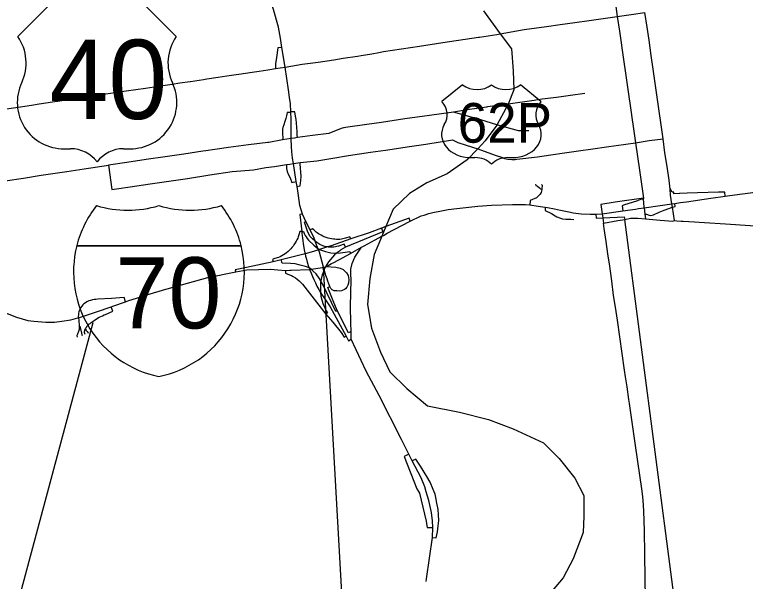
# Model space of a CAD drawing. Extents: x -1146 to -445, y -1283 to -822.
# Drawn here: x -909.25 to -877.16, y -1082.3 to -1057.42 of the extents above; entities that cross this region are included whole.
import ezdxf

# ---------------------------------------------------------------- set-up
doc = ezdxf.new("R2010")
doc.units = 0
for name, color, linetype in [('Default', 7, 'Continuous'), ('GM_P_US_Alignment', 7, 'Continuous'), ('GM_P_US_Shield', 7, 'Continuous'), ('GM_X_Interchange_Ramps', 7, 'Continuous'), ('GM_X_Interstate_Route', 7, 'Continuous'), ('GM_X_Interstate_Shield', 7, 'Continuous'), ('GM_X_State_Route', 7, 'Continuous'), ('GM_X_Township', 7, 'Continuous'), ('GM_X_US_Route', 7, 'Continuous'), ('GM_X_US_Shield', 7, 'Continuous')]:
    doc.layers.add(name, color=color, linetype=linetype)

msp = doc.modelspace()

# ---------------------------------------------------------------- linework, layer by layer
at = {"layer": 'Default'}
for points in [[(-877.164, -1087.481), (-879.711, -1087.481), (-882.459, -1066.411)], [(-897.172, -1087.481), (-894.625, -1087.481), (-895.684, -1068.512)], [(-914.692, -1094.509), (-912.144, -1094.509), (-905.796, -1070.942)]]:
    msp.add_lwpolyline(points, dxfattribs=at)
at = {"layer": 'GM_P_US_Alignment'}
msp.add_lwpolyline([(-886.673, -1062.523), (-887.13, -1062.531), (-888.071, -1062.256), (-888.783, -1062.047), (-889.976, -1061.698)], dxfattribs=at)
at = {"layer": 'GM_P_US_Shield'}
for p, q in [((-889.583, -1060.507), (-890.489, -1061.232)), ((-886.139, -1061.232), (-887.045, -1060.507)), ((-889.22, -1063.698), (-889.039, -1063.698)), ((-887.589, -1063.698), (-887.408, -1063.698))]:
    msp.add_line(p, q, dxfattribs=at)
for centre, major_axis, start_param, end_param in [((-888.948, -1059.989), (-0.906, 0), 0.795399, 2.346194), ((-887.68, -1059.989), (-0.906, 0), 0.795399, 2.346194), ((-891.529, -1061.815), (1.269, 0), 5.838949, 6.894067), ((-885.099, -1061.815), (-1.269, 0), 5.672304, 6.727422), ((-889.235, -1062.683), (1.269, 0), 2.702327, 4.723529), ((-887.393, -1062.683), (-1.269, 0), 1.559657, 3.580859), ((-889.039, -1064.423), (-0.906, 0), 3.785094, 4.712389), ((-887.589, -1064.423), (-0.906, 0), 4.712389, 5.639684)]:
    msp.add_ellipse(centre, major_axis=major_axis, ratio=0.8, start_param=start_param, end_param=end_param, dxfattribs=at)
at = {"layer": 'GM_X_Interchange_Ramps'}
for points in [[(-897.519, -1058.866), (-897.688, -1058.887), (-897.748, -1059.306), (-897.793, -1059.586), (-897.799, -1059.663), (-897.793, -1059.788)], [(-897.117, -1061.72), (-897.29, -1061.721), (-897.318, -1061.861), (-897.345, -1061.984), (-897.382, -1062.115), (-897.432, -1062.257), (-897.474, -1062.374), (-897.488, -1062.458), (-897.494, -1062.646), (-897.471, -1062.852), (-897.488, -1062.92)], [(-896.826, -1062.823), (-896.843, -1062.711), (-896.848, -1062.547), (-896.856, -1062.374), (-896.873, -1062.174), (-896.893, -1062.025), (-896.915, -1061.882), (-896.944, -1061.689), (-897.117, -1061.691)], [(-897.314, -1064.007), (-897.316, -1064.056), (-897.316, -1064.177), (-897.278, -1064.307), (-897.238, -1064.425), (-897.156, -1064.594), (-897.079, -1064.793), (-896.89, -1064.748)], [(-896.85, -1064.967), (-896.715, -1064.945), (-896.681, -1064.7), (-896.665, -1064.529), (-896.716, -1063.978), (-896.719, -1063.918)], [(-886.123, -1064.876), (-886.091, -1064.913), (-886.101, -1065.081), (-886.122, -1065.179), (-886.137, -1065.227), (-886.182, -1065.301), (-886.236, -1065.363), (-886.343, -1065.459), (-886.613, -1065.582), (-886.633, -1065.779)], [(-886.381, -1064.869), (-886.372, -1064.925), (-886.322, -1064.938), (-886.291, -1064.951), (-886.2, -1065.029), (-886.164, -1065.075), (-886.101, -1065.081)], [(-880.308, -1065.256), (-880.313, -1065.219), (-880.363, -1065.21), (-880.399, -1065.181), (-880.419, -1065.141), (-880.433, -1065.088), (-880.464, -1065.091)], [(-878.045, -1065.391), (-878.071, -1065.209), (-878.349, -1065.217), (-879.718, -1065.258), (-880.043, -1065.272), (-880.06, -1065.274), (-880.304, -1065.293), (-880.308, -1065.256)], [(-881.659, -1065.527), (-881.767, -1065.541), (-881.901, -1065.598), (-882.518, -1065.793), (-882.579, -1065.814), (-882.544, -1066.035)], [(-885.958, -1065.871), (-885.962, -1066.024), (-885.673, -1066.158), (-885.518, -1066.25), (-885.437, -1066.303), (-885.284, -1066.353), (-885.191, -1066.379), (-885.051, -1066.402), (-884.827, -1066.405), (-884.698, -1066.409)], [(-881.576, -1066.187), (-881.505, -1066.186), (-881.385, -1066.23), (-881.318, -1066.238), (-881.264, -1066.23), (-881.197, -1066.21), (-880.954, -1066.094), (-880.727, -1066.004), (-880.371, -1065.877), (-880.252, -1065.839), (-880.265, -1065.708)], [(-896.616, -1066.176), (-896.721, -1066.197), (-896.638, -1066.943), (-896.634, -1067.027), (-896.626, -1067.124), (-896.614, -1067.237), (-896.602, -1067.343), (-896.581, -1067.488), (-896.556, -1067.639), (-896.534, -1067.753), (-896.508, -1067.878), (-896.499, -1067.917), (-896.475, -1068.018), (-896.439, -1068.156), (-896.4, -1068.293), (-896.341, -1068.479), (-896.319, -1068.542), (-896.297, -1068.605), (-896.232, -1068.777), (-896.177, -1068.91), (-896.118, -1069.045), (-896.047, -1069.197), (-895.975, -1069.34), (-895.895, -1069.488), (-895.815, -1069.626), (-895.774, -1069.696), (-895.577, -1069.984), (-895.394, -1070.253), (-894.695, -1071.535), (-894.585, -1071.737), (-894.476, -1071.673)], [(-883.724, -1066.179), (-883.723, -1066.364), (-883.427, -1066.348), (-882.481, -1066.293), (-882.459, -1066.411)], [(-891.879, -1066.487), (-891.931, -1066.353), (-892.948, -1066.726), (-893.139, -1066.803), (-893.677, -1067.001), (-894.495, -1067.268), (-895.358, -1067.57), (-895.511, -1067.619), (-895.869, -1067.733), (-895.908, -1067.746), (-896.135, -1067.818), (-896.499, -1067.917), (-897.024, -1068.058), (-897.551, -1068.186), (-897.896, -1068.269), (-899.069, -1068.518), (-899.566, -1068.623), (-899.542, -1068.711)], [(-894.73, -1067.63), (-894.786, -1067.5), (-895.032, -1067.593), (-895.23, -1067.623), (-895.463, -1067.625), (-895.511, -1067.619), (-895.585, -1067.609), (-895.713, -1067.577), (-895.846, -1067.513), (-895.985, -1067.422), (-896.053, -1067.363), (-896.166, -1067.263), (-896.288, -1067.14), (-896.395, -1066.922), (-896.517, -1066.533), (-896.463, -1066.508)], [(-894.495, -1067.268), (-894.534, -1067.178), (-894.728, -1067.24), (-894.835, -1067.265), (-894.896, -1067.28), (-894.977, -1067.287), (-895.052, -1067.29), (-895.122, -1067.289), (-895.193, -1067.285), (-895.25, -1067.279), (-895.331, -1067.267), (-895.413, -1067.251), (-895.482, -1067.233), (-895.568, -1067.206), (-895.657, -1067.172), (-895.721, -1067.143), (-895.792, -1067.107), (-895.851, -1067.074), (-895.908, -1067.038), (-895.966, -1066.998), (-896.007, -1066.967), (-896.069, -1066.916), (-896.118, -1066.871), (-896.17, -1066.82), (-896.28, -1066.87)], [(-893.139, -1066.803), (-893.079, -1066.957), (-894.73, -1067.63), (-894.921, -1067.748), (-894.993, -1067.798), (-895.079, -1067.863), (-895.111, -1067.892), (-895.199, -1067.968), (-895.294, -1068.064), (-895.381, -1068.165), (-895.462, -1068.271), (-895.541, -1068.393), (-895.597, -1068.493), (-895.655, -1068.616), (-895.677, -1068.664), (-895.74, -1068.839), (-895.789, -1069.032), (-895.803, -1069.121), (-895.814, -1069.188), (-895.827, -1069.342), (-895.826, -1069.519), (-895.815, -1069.626), (-895.799, -1069.773), (-895.762, -1069.942), (-895.714, -1070.095), (-895.633, -1070.293), (-895.568, -1070.417), (-895.512, -1070.51), (-895.579, -1070.564)], [(-896.638, -1066.943), (-896.724, -1066.945), (-896.771, -1067.085), (-896.801, -1067.18), (-896.822, -1067.234), (-896.862, -1067.302), (-896.893, -1067.368), (-896.932, -1067.441), (-896.985, -1067.526), (-897.023, -1067.58), (-897.073, -1067.644), (-897.127, -1067.707), (-897.179, -1067.76), (-897.244, -1067.82), (-897.313, -1067.877), (-897.378, -1067.924), (-897.446, -1067.968), (-897.513, -1068.006), (-897.595, -1068.047), (-897.665, -1068.078), (-897.726, -1068.1), (-897.863, -1068.146), (-897.928, -1068.165), (-897.896, -1068.269)], [(-896.638, -1066.943), (-896.569, -1066.941), (-896.535, -1067.029), (-896.49, -1067.112), (-896.45, -1067.179), (-896.399, -1067.254), (-896.343, -1067.327), (-896.113, -1067.541), (-895.931, -1067.684), (-895.869, -1067.733), (-895.597, -1067.823), (-895.369, -1067.877), (-895.183, -1067.895), (-895.111, -1067.892), (-894.938, -1067.883), (-894.53, -1067.823), (-894.503, -1067.901)], [(-895.084, -1070.414), (-895.152, -1070.448), (-895.735, -1069.237), (-895.803, -1069.121), (-895.878, -1068.993), (-896.017, -1068.802), (-896.143, -1068.679), (-896.237, -1068.602), (-896.319, -1068.542), (-896.484, -1068.475), (-896.708, -1068.413), (-896.927, -1068.356), (-897.142, -1068.346), (-897.51, -1068.336), (-897.551, -1068.186)], [(-897.355, -1068.649), (-897.351, -1068.778), (-897.188, -1068.837), (-897.093, -1068.879), (-897.015, -1068.92), (-896.925, -1068.975), (-896.843, -1069.034), (-896.758, -1069.105), (-896.692, -1069.168), (-896.609, -1069.26), (-895.579, -1070.564), (-895.273, -1070.914), (-894.914, -1071.37), (-894.776, -1071.58), (-894.695, -1071.535)], [(-894.476, -1071.33), (-894.585, -1071.389), (-895.084, -1070.414), (-895.265, -1069.981), (-895.492, -1069.398), (-895.415, -1069.352)], [(-904.386, -1070.031), (-904.447, -1069.842), (-904.998, -1069.878), (-905.595, -1069.916), (-905.683, -1069.922), (-905.753, -1069.931), (-905.837, -1069.946), (-905.916, -1069.966), (-905.997, -1069.992), (-906.081, -1070.031), (-906.144, -1070.07), (-906.206, -1070.118), (-906.255, -1070.164), (-906.303, -1070.221), (-906.339, -1070.271), (-906.373, -1070.329), (-906.403, -1070.395), (-906.426, -1070.462), (-906.441, -1070.522), (-906.453, -1070.604), (-906.456, -1070.676), (-906.453, -1070.73), (-906.452, -1070.748), (-906.439, -1070.827), (-906.417, -1071.096), (-906.415, -1071.141), (-906.417, -1071.193), (-906.422, -1071.241), (-906.431, -1071.286), (-906.444, -1071.333), (-906.456, -1071.37), (-906.473, -1071.41), (-906.491, -1071.448), (-906.526, -1071.509), (-906.5, -1071.586)], [(-906.007, -1071.415), (-906.033, -1071.341), (-906.068, -1071.328), (-906.092, -1071.305), (-906.113, -1071.263), (-906.128, -1071.208), (-906.105, -1071.151), (-906.085, -1071.121), (-906.062, -1071.087), (-906.028, -1071.048), (-905.989, -1071.011), (-905.941, -1070.973), (-905.888, -1070.933), (-905.82, -1070.885), (-905.749, -1070.837), (-905.678, -1070.792), (-905.607, -1070.749), (-905.532, -1070.707), (-905.472, -1070.676), (-905.399, -1070.64), (-905.326, -1070.606), (-905.264, -1070.579), (-904.946, -1070.442), (-905.005, -1070.247)], [(-906.417, -1071.096), (-906.386, -1071.09), (-906.321, -1071.408), (-906.285, -1071.512)], [(-906.151, -1071.465), (-906.182, -1071.376), (-906.178, -1071.332), (-906.167, -1071.281), (-906.15, -1071.208), (-906.128, -1071.208)], [(-891.94, -1076.709), (-892.154, -1076.816), (-891.595, -1078.243), (-891.52, -1078.358)], [(-890.833, -1078.37), (-890.879, -1078.263), (-891.012, -1077.946), (-891.151, -1077.701), (-891.428, -1077.238), (-891.641, -1076.927), (-891.79, -1077.001)], [(-891.52, -1078.358), (-891.471, -1078.433), (-891.177, -1079.661), (-891.146, -1079.858), (-891.138, -1079.938), (-890.886, -1079.931)], [(-890.907, -1080.368), (-890.745, -1080.382), (-890.684, -1080.119), (-890.647, -1079.855), (-890.631, -1079.62), (-890.64, -1079.37), (-890.656, -1079.141), (-890.709, -1078.87), (-890.755, -1078.613), (-890.791, -1078.465), (-890.833, -1078.37)]]:
    msp.add_lwpolyline(points, dxfattribs=at)
at = {"layer": 'GM_X_Interstate_Route'}
for points in [[(-877.844, -1065.363), (-876.737, -1065.211), (-875.497, -1065.029)], [(-879.752, -1065.637), (-878.681, -1065.486), (-878.045, -1065.391), (-877.844, -1065.363)], [(-891.274, -1066.22), (-891.068, -1066.157), (-890.895, -1066.109), (-890.503, -1066.029), (-890.215, -1065.98), (-889.834, -1065.937)], [(-889.834, -1065.937), (-888.915, -1065.832), (-888.319, -1065.793), (-887.384, -1065.755), (-887.371, -1065.755), (-886.825, -1065.752), (-886.633, -1065.779)], [(-886.633, -1065.779), (-886.263, -1065.831), (-885.958, -1065.871), (-885.846, -1065.893)], [(-885.846, -1065.893), (-885.549, -1065.95), (-885.285, -1066.003)], [(-881.985, -1065.955), (-881.851, -1065.936), (-881.613, -1065.901)], [(-881.613, -1065.901), (-880.899, -1065.803), (-880.389, -1065.725), (-880.265, -1065.708)], [(-880.265, -1065.708), (-880.02, -1065.675), (-879.752, -1065.637)], [(-892.892, -1067.022), (-892.582, -1066.856), (-891.879, -1066.487), (-891.402, -1066.259), (-891.274, -1066.22)], [(-885.285, -1066.003), (-885.28, -1066.004), (-884.837, -1066.094)], [(-884.837, -1066.094), (-884.725, -1066.117)], [(-884.725, -1066.117), (-884.38, -1066.17), (-883.978, -1066.185), (-883.724, -1066.179)], [(-883.724, -1066.179), (-883.449, -1066.17), (-882.544, -1066.035), (-881.985, -1065.955)], [(-893.9, -1067.567), (-893.416, -1067.31), (-893.121, -1067.146), (-893.059, -1067.112), (-892.892, -1067.022)], [(-895.335, -1068.353), (-895.271, -1068.315), (-895.019, -1068.187), (-894.503, -1067.901), (-894.013, -1067.626)], [(-894.487, -1068.823), (-894.489, -1068.768), (-894.484, -1068.59), (-894.435, -1068.348), (-894.319, -1068.072), (-894.013, -1067.626)], [(-894.013, -1067.626), (-893.9, -1067.567)], [(-897.107, -1068.642), (-896.297, -1068.605), (-896.237, -1068.602), (-895.732, -1068.522), (-895.684, -1068.512), (-895.597, -1068.493), (-895.56, -1068.485), (-895.335, -1068.353)], [(-902.546, -1069.452), (-900.764, -1068.957), (-899.542, -1068.711), (-899.055, -1068.621)], [(-899.055, -1068.621), (-898.545, -1068.608), (-898.034, -1068.602)], [(-898.034, -1068.602), (-898.016, -1068.602), (-897.695, -1068.625)], [(-897.695, -1068.625), (-897.355, -1068.649), (-897.173, -1068.645), (-897.107, -1068.642)], [(-894.476, -1071.445), (-894.476, -1071.33), (-894.489, -1070.952), (-894.5, -1070.231), (-894.479, -1069.045), (-894.487, -1068.823)], [(-903.897, -1069.869), (-903.448, -1069.725), (-902.617, -1069.472), (-902.546, -1069.452)], [(-906.482, -1070.738), (-906.453, -1070.73), (-905.661, -1070.473), (-905.005, -1070.247), (-904.94, -1070.224), (-904.386, -1070.031), (-904.234, -1069.977), (-903.904, -1069.871), (-903.897, -1069.869)], [(-909.896, -1070.396), (-909.65, -1070.516), (-909.171, -1070.707), (-908.919, -1070.78), (-908.667, -1070.842), (-908.405, -1070.881), (-907.878, -1070.92), (-907.505, -1070.914), (-907.178, -1070.874), (-906.778, -1070.815), (-906.482, -1070.738)], [(-891.865, -1076.855), (-891.94, -1076.709), (-892.267, -1076.074), (-893.24, -1074.134), (-893.808, -1073.075), (-894.476, -1071.673), (-894.476, -1071.445)], [(-891.185, -1082.297), (-891.165, -1082.179), (-890.907, -1080.368), (-890.886, -1079.931), (-890.896, -1079.643), (-890.95, -1079.27), (-891.062, -1078.744), (-891.181, -1078.361), (-891.246, -1078.147), (-891.407, -1077.747), (-891.79, -1077.001), (-891.865, -1076.855)]]:
    msp.add_lwpolyline(points, dxfattribs=at)
at = {"layer": 'GM_X_Interstate_Shield'}
for p, q in [((-906.521, -1067.564), (-899.307, -1067.564)), ((-899.307, -1067.564), (-906.521, -1067.564)), ((-899.307, -1067.564), (-906.521, -1067.564))]:
    msp.add_line(p, q, dxfattribs=at)
for centre, start, end in [((-901.977, -1068.713), 141.669, 165.8066), ((-904.284, -1061.323), 253.0091, 286.9909), ((-901.544, -1061.323), 253.0091, 286.9909), ((-903.852, -1068.713), 14.1934, 38.331), ((-901.977, -1068.713), 165.8066, 258.463), ((-903.852, -1068.713), 281.537, 14.1934)]:
    msp.add_arc(centre, 4.688, start, end, dxfattribs=at)
at = {"layer": 'GM_X_State_Route'}
for points in [[(-897.376, -1059.726), (-897.519, -1058.866), (-897.583, -1058.461), (-897.66, -1057.969), (-897.878, -1057.195), (-898.177, -1056.359), (-898.222, -1056.234)], [(-897.111, -1062.866), (-897.112, -1062.306), (-897.108, -1061.984), (-897.117, -1061.72), (-897.117, -1061.691), (-897.141, -1061.345), (-897.182, -1061.066), (-897.231, -1060.72), (-897.376, -1059.726)], [(-897.012, -1063.959), (-897.046, -1063.731), (-897.081, -1063.425), (-897.099, -1063.221), (-897.111, -1062.866)], [(-896.805, -1065.264), (-896.85, -1064.967), (-896.89, -1064.748), (-897.012, -1063.959)], [(-895.535, -1069.025), (-895.585, -1068.873), (-895.655, -1068.616), (-895.684, -1068.512), (-895.868, -1067.851), (-895.908, -1067.746), (-895.931, -1067.684), (-896.053, -1067.363), (-896.103, -1067.231), (-896.28, -1066.87), (-896.463, -1066.508), (-896.616, -1066.176), (-896.725, -1065.8), (-896.805, -1065.264)], [(-895.56, -1068.485), (-895.154, -1068.51), (-894.963, -1068.546), (-894.827, -1068.608), (-894.674, -1068.75), (-894.6, -1068.867), (-894.575, -1069.051), (-894.587, -1069.211), (-894.614, -1069.298), (-894.666, -1069.389), (-894.722, -1069.461), (-894.764, -1069.492), (-894.901, -1069.55), (-895.006, -1069.556), (-895.107, -1069.55), (-895.221, -1069.544), (-895.314, -1069.507), (-895.355, -1069.457)], [(-895.355, -1069.457), (-895.369, -1069.439), (-895.415, -1069.352), (-895.505, -1069.119), (-895.535, -1069.025)]]:
    msp.add_lwpolyline(points, dxfattribs=at)
at = {"layer": 'GM_X_Township'}
msp.add_lwpolyline([(-888.663, -1057.26), (-887.936, -1058.273), (-887.434, -1058.922), (-887.362, -1059.897), (-887.326, -1060.728), (-887.586, -1061.351), (-888.085, -1062.282), (-888.59, -1062.968), (-888.919, -1063.312), (-889.385, -1063.799), (-890.252, -1064.414), (-891.155, -1064.811), (-891.914, -1065.281), (-892.637, -1065.967), (-892.948, -1066.726), (-893.121, -1067.146), (-893.181, -1067.293), (-893.468, -1067.955), (-893.648, -1069.003), (-893.757, -1070.141), (-893.576, -1071.189), (-893.179, -1072.237), (-892.782, -1073.104), (-892.023, -1073.827), (-891.12, -1074.586), (-889.711, -1074.875), (-888.446, -1075.2), (-887.363, -1075.598), (-886.026, -1076.212), (-885.34, -1076.899), (-884.653, -1077.766), (-884.256, -1078.525), (-884.256, -1078.679), (-884.256, -1079.429), (-884.292, -1080.151), (-884.726, -1081.308), (-885.16, -1082.139), (-885.81, -1082.898)], dxfattribs=at)
at = {"layer": 'GM_X_US_Route'}
for points in [[(-883.147, -1055.005), (-883.054, -1055.628), (-882.972, -1056.233), (-882.881, -1056.841), (-882.793, -1057.505)], [(-884.655, -1057.765), (-884.022, -1057.682), (-882.793, -1057.505)], [(-882.793, -1057.505), (-882.175, -1057.414), (-881.574, -1057.333)], [(-882.793, -1057.505), (-882.698, -1058.149), (-882.518, -1059.391), (-882.433, -1059.997), (-882.344, -1060.612)], [(-881.131, -1060.434), (-881.214, -1059.825), (-881.303, -1059.219), (-881.392, -1058.54), (-881.474, -1057.98), (-881.574, -1057.333)], [(-886.871, -1058.075), (-886.871, -1058.075), (-885.892, -1057.944), (-885.291, -1057.858), (-884.655, -1057.765)], [(-888.86, -1058.412), (-888.837, -1058.409), (-888.082, -1058.295), (-887.936, -1058.273), (-886.871, -1058.075)], [(-897.376, -1059.726), (-896.625, -1059.597), (-895.93, -1059.513), (-895.237, -1059.406), (-894.829, -1059.34), (-894.201, -1059.24), (-894.028, -1059.212), (-893.572, -1059.141), (-893.266, -1059.093), (-893.048, -1059.044), (-891.479, -1058.807), (-890.447, -1058.652), (-888.886, -1058.416), (-888.86, -1058.412)], [(-904.356, -1060.775), (-903.929, -1060.712), (-903.508, -1060.646), (-903.13, -1060.588), (-902.749, -1060.528), (-902.33, -1060.472), (-901.991, -1060.423), (-901.539, -1060.356), (-901.53, -1060.355), (-900.955, -1060.268), (-900.816, -1060.247), (-900.318, -1060.175), (-899.929, -1060.117), (-899.524, -1060.056), (-899.404, -1060.038), (-898.826, -1059.951), (-898.508, -1059.902), (-898.136, -1059.843), (-897.793, -1059.788), (-897.585, -1059.757)], [(-897.585, -1059.757), (-897.376, -1059.726)], [(-880.947, -1061.656), (-881.131, -1060.434)], [(-914.819, -1062.321), (-913.89, -1062.184), (-912.998, -1062.052), (-912.029, -1061.91), (-910.966, -1061.753), (-910.145, -1061.639), (-909.298, -1061.515), (-909.101, -1061.484), (-908.513, -1061.4), (-908.167, -1061.343), (-907.595, -1061.257), (-907.266, -1061.209), (-906.644, -1061.112), (-906.549, -1061.094), (-905.544, -1060.951), (-904.747, -1060.832), (-904.356, -1060.775)], [(-882.344, -1060.612), (-882.169, -1061.825), (-882.168, -1061.83)], [(-884.211, -1060.88), (-884.84, -1060.967), (-885.461, -1061.057), (-886.085, -1061.141), (-886.364, -1061.183), (-886.439, -1061.194)], [(-886.439, -1061.194), (-887.586, -1061.351), (-888.483, -1061.474), (-888.536, -1061.482)], [(-888.536, -1061.482), (-889.272, -1061.593), (-889.976, -1061.698), (-891.032, -1061.852), (-892.124, -1061.998), (-893.139, -1062.158), (-893.789, -1062.249), (-894.723, -1062.381)], [(-880.778, -1062.872), (-880.864, -1062.266), (-880.947, -1061.656)], [(-882.168, -1061.83), (-882.082, -1062.435), (-881.989, -1063.047)], [(-894.723, -1062.381), (-894.779, -1062.389), (-894.809, -1062.393), (-894.908, -1062.424), (-895.456, -1062.636), (-896.169, -1062.724), (-896.617, -1062.792), (-896.826, -1062.823), (-896.907, -1062.835), (-896.958, -1062.843)], [(-898.131, -1063.041), (-898.981, -1063.133), (-899.865, -1063.259), (-900.351, -1063.328), (-900.462, -1063.344), (-900.464, -1063.345)], [(-897.488, -1062.92), (-898.089, -1063.037), (-898.131, -1063.041)], [(-896.958, -1062.843), (-897.111, -1062.866), (-897.488, -1062.92)], [(-897.012, -1063.959), (-896.719, -1063.918), (-895.98, -1063.834), (-895.286, -1063.724), (-894.589, -1063.609), (-893.629, -1063.463), (-892.962, -1063.378), (-891.912, -1063.213), (-891.197, -1063.112), (-890.024, -1062.919)], [(-890.024, -1062.919), (-889.79, -1063.03), (-889.421, -1063.15)], [(-883.866, -1063.308), (-883.256, -1063.222), (-881.989, -1063.047)], [(-881.989, -1063.047), (-881.389, -1062.954), (-880.778, -1062.872)], [(-881.989, -1063.047), (-881.897, -1063.655), (-881.815, -1064.256), (-881.728, -1064.868), (-881.639, -1065.48)], [(-880.445, -1065.343), (-880.464, -1065.091), (-880.515, -1064.696), (-880.601, -1064.089), (-880.697, -1063.483), (-880.778, -1062.872)], [(-900.464, -1063.345), (-900.859, -1063.402), (-900.988, -1063.421), (-901.816, -1063.543), (-902.638, -1063.663), (-903.472, -1063.786), (-904.33, -1063.911), (-905.122, -1064.028)], [(-889.421, -1063.15), (-888.919, -1063.312), (-888.154, -1063.59), (-887.831, -1063.701)], [(-887.193, -1063.771), (-886.294, -1063.66), (-885.707, -1063.579), (-885.1, -1063.492), (-884.494, -1063.405), (-883.866, -1063.308)], [(-887.831, -1063.701), (-887.735, -1063.734), (-887.598, -1063.762), (-887.415, -1063.781), (-887.271, -1063.78), (-887.193, -1063.771)], [(-904.976, -1065.102), (-904.778, -1065.072), (-904.185, -1064.984), (-903.305, -1064.852), (-902.482, -1064.729), (-901.667, -1064.615), (-900.674, -1064.459), (-899.699, -1064.314), (-898.769, -1064.229), (-898.226, -1064.135), (-897.843, -1064.083), (-897.314, -1064.007), (-897.163, -1063.983)], [(-897.163, -1063.983), (-897.012, -1063.959)], [(-910.509, -1064.845), (-909.666, -1064.717), (-908.862, -1064.595), (-908.085, -1064.477), (-906.962, -1064.307), (-906.202, -1064.191), (-905.122, -1064.028)], [(-905.122, -1064.028), (-904.976, -1065.102)], [(-881.639, -1065.48), (-882.876, -1065.658), (-883.509, -1065.751)], [(-881.639, -1065.48), (-881.659, -1065.527), (-881.618, -1065.857)], [(-880.389, -1065.725), (-880.445, -1065.343)], [(-883.509, -1065.751), (-883.45, -1066.162)], [(-881.618, -1065.857), (-881.613, -1065.901), (-881.576, -1066.187), (-881.55, -1066.387)], [(-880.272, -1066.465), (-880.371, -1065.877), (-880.389, -1065.725)], [(-883.45, -1066.162), (-883.449, -1066.17), (-883.427, -1066.348), (-883.394, -1066.574)], [(-883.394, -1066.574), (-882.77, -1066.466), (-882.459, -1066.411), (-882.205, -1066.361), (-881.886, -1066.354), (-881.55, -1066.387)], [(-881.585, -1080.769), (-881.59, -1080.422), (-881.595, -1080.062), (-881.63, -1079.222), (-881.65, -1078.732), (-881.687, -1078.452), (-881.718, -1078.234), (-881.886, -1077.043), (-882.004, -1076.237), (-882.107, -1075.522), (-882.251, -1074.496), (-882.276, -1074.321), (-882.359, -1073.764), (-882.426, -1073.316), (-882.467, -1073.034), (-882.573, -1072.302), (-882.677, -1071.565), (-882.78, -1070.835), (-882.865, -1070.263), (-882.95, -1069.747), (-883.027, -1069.109), (-883.042, -1069.01), (-883.121, -1068.465), (-883.204, -1067.917), (-883.279, -1067.377), (-883.36, -1066.804), (-883.394, -1066.574)], [(-881.55, -1066.387), (-880.901, -1066.443), (-880.343, -1066.491), (-880.272, -1066.465)], [(-880.272, -1066.465), (-880.172, -1066.476), (-879.99, -1066.489), (-879.933, -1066.493), (-879.896, -1066.495), (-879.642, -1066.506), (-879.404, -1066.525), (-879.197, -1066.538), (-878.954, -1066.552), (-878.041, -1066.613), (-877.82, -1066.626), (-876.53, -1066.706)], [(-881.197, -1093.672), (-881.197, -1093.672), (-881.216, -1093.057), (-881.238, -1092.336), (-881.273, -1091.408), (-881.298, -1090.477), (-881.328, -1089.537), (-881.339, -1089.202), (-881.357, -1088.513), (-881.399, -1087.547), (-881.422, -1086.672), (-881.427, -1086.508), (-881.453, -1085.805), (-881.48, -1084.882), (-881.504, -1084.154), (-881.51, -1083.943), (-881.533, -1083.271), (-881.562, -1082.373), (-881.584, -1080.898), (-881.585, -1080.769)]]:
    msp.add_lwpolyline(points, dxfattribs=at)
at = {"layer": 'GM_X_US_Shield'}
for p, q in [((-907.662, -1056.929), (-909.112, -1058.379)), ((-902.151, -1058.379), (-903.602, -1056.929)), ((-907.082, -1063.31), (-906.792, -1063.31)), ((-904.472, -1063.31), (-904.182, -1063.31))]:
    msp.add_line(p, q, dxfattribs=at)
for centre, radius, start, end in [((-910.775, -1059.544), 2.03, 334.5471, 35.0009), ((-900.488, -1059.544), 2.03, 144.9991, 205.4529), ((-907.105, -1061.28), 2.03, 154.8319, 270.6383), ((-904.159, -1061.28), 2.03, 269.3617, 25.1681), ((-906.792, -1064.76), 1.45, 36.8699, 90), ((-904.472, -1064.76), 1.45, 90, 143.1301)]:
    msp.add_arc(centre, radius, start, end, dxfattribs=at)

# ---------------------------------------------------------------- texts
at = {"layer": 'GM_P_US_Shield'}
msp.add_text('62P', height=1.7402, dxfattribs=at).set_placement((-889.795, -1063.045))
at = {"layer": 'GM_X_Interstate_Shield'}
msp.add_text('70', height=3.125, dxfattribs=at).set_placement((-904.821, -1071.197))
at = {"layer": 'GM_X_US_Shield'}
msp.add_text('40', height=3.4805, dxfattribs=at).set_placement((-907.723, -1062.005))

doc.saveas('drawing.dxf')
